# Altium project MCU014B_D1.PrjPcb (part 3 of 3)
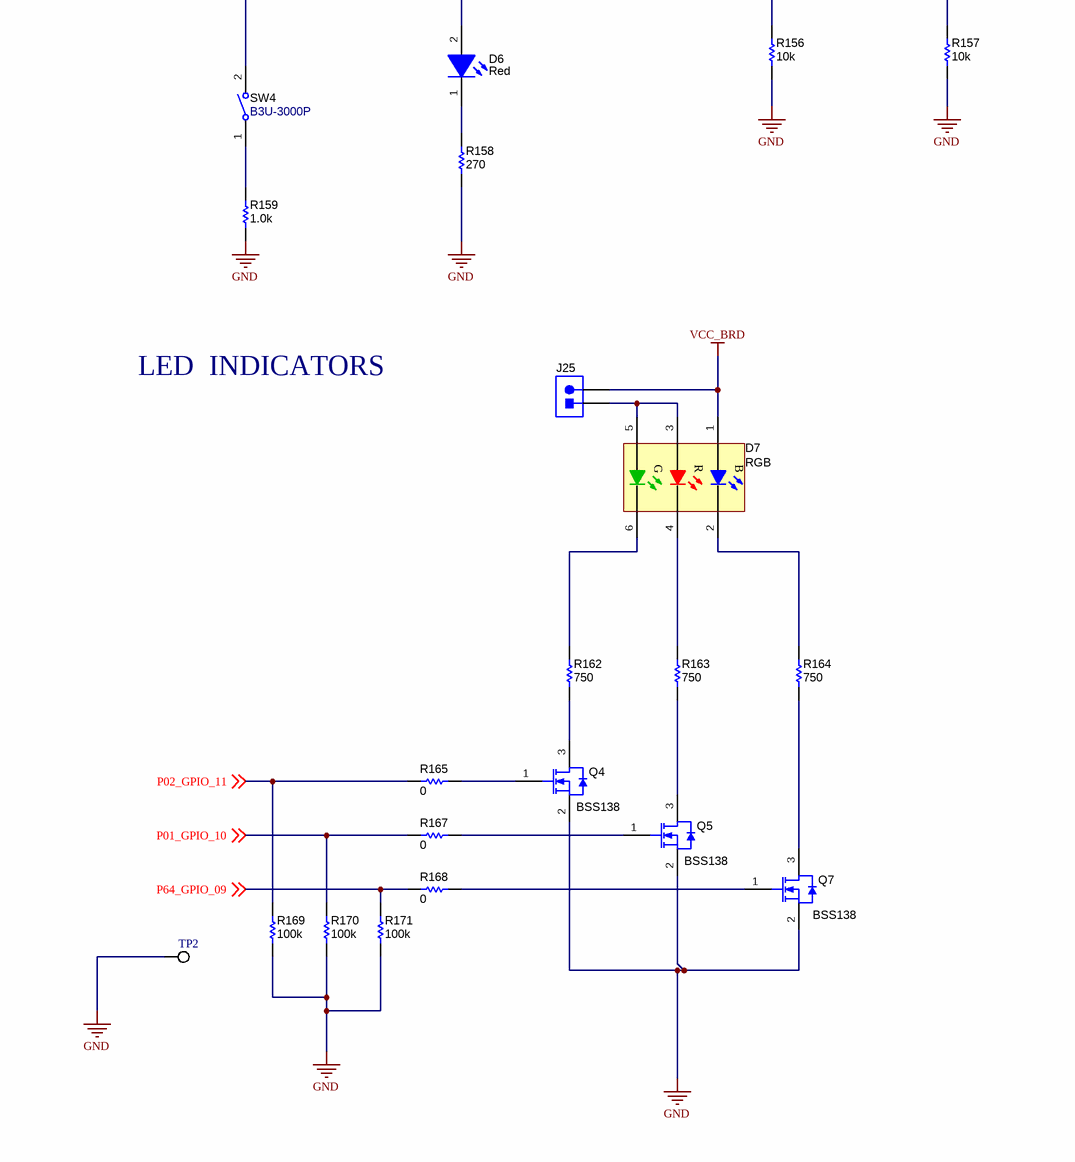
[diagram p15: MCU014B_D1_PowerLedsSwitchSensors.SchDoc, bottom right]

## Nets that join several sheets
GND: MCU014B_D1_AntennaRFSection (29 pins), MCU014B_D1_EmulationCircuit (66 pins), MCU014B_D1_EngineArea (42 pins), MCU014B_D1_HostInterface_ADC (15 pins), MCU014B_D1_PowerLedsSwitchSensors (41 pins)
VBAT_CC: MCU014B_D1_EmulationCircuit (J11.3 J11.4 R37.2), MCU014B_D1_EngineArea (13 pins), MCU014B_D1_HostInterface_ADC (R64.1), MCU014B_D1_PowerLedsSwitchSensors (5 pins)
VBUS_USB1: MCU014B_D1_EmulationCircuit (L5.2 R8.1 R15.1), MCU014B_D1_PowerLedsSwitchSensors (C80.1 J23.2 U14.2 U14.3)
VCC_5V: MCU014B_D1_HostInterface_ADC (P2.2), MCU014B_D1_PowerLedsSwitchSensors (J23.1 J27.1)
VCC_BRD: MCU014B_D1_EmulationCircuit (R35.1), MCU014B_D1_EngineArea (J14.3 R42.2), MCU014B_D1_HostInterface_ADC (J18.1 R66.1), MCU014B_D1_PowerLedsSwitchSensors (16 pins)
VCC_BUFFER: MCU014B_D1_EmulationCircuit (10 pins), MCU014B_D1_PowerLedsSwitchSensors (J22.1)
VCC_LDO_3V3: MCU014B_D1_EmulationCircuit (37 pins), MCU014B_D1_PowerLedsSwitchSensors (8 pins)
A_RX: MCU014B_D1_AntennaRFSection (C9.2), MCU014B_D1_EngineArea (U10.27)
A_TX: MCU014B_D1_AntennaRFSection (C10.2), MCU014B_D1_EngineArea (U10.28)
CC_COEX_BLE: MCU014B_D1_EngineArea (U10.50), MCU014B_D1_HostInterface_ADC (R61.1 R62.1 R101.2 R102.1)
CC_COEX_SW_OUT: MCU014B_D1_EngineArea (U10.58), MCU014B_D1_HostInterface_ADC (R60.1 R63.1 R123.2)
CC_COEX_WAKEUP: MCU014B_D1_EngineArea (U10.18), MCU014B_D1_HostInterface_ADC (R69.2 R78.1)
CC_nRESET: MCU014B_D1_EmulationCircuit (J4.10 J8.10 Q1.1 SW1.4), MCU014B_D1_EngineArea (C49.1 J13.2 R41.2 U10.32), MCU014B_D1_PowerLedsSwitchSensors (D5.1)
LP_GPIO_01: MCU014B_D1_EmulationCircuit (J9.1), MCU014B_D1_HostInterface_ADC (R91.2)
LP_GPIO_02: MCU014B_D1_EmulationCircuit (J10.1), MCU014B_D1_HostInterface_ADC (C72.1 R112.1 R116.2)
LP_RESET_OUT: MCU014B_D1_HostInterface_ADC (P1.10), MCU014B_D1_PowerLedsSwitchSensors (D5.2 R152.2)
P01_GPIO_10: MCU014B_D1_EmulationCircuit (J11.9), MCU014B_D1_EngineArea (U10.1), MCU014B_D1_HostInterface_ADC (R68.1 R98.1), MCU014B_D1_PowerLedsSwitchSensors (R132.1 R167.1 R170.1)
P02_GPIO_11: MCU014B_D1_EmulationCircuit (J11.11), MCU014B_D1_EngineArea (U10.2), MCU014B_D1_HostInterface_ADC (R67.1 R100.1), MCU014B_D1_PowerLedsSwitchSensors (R139.1 R165.1 R169.1)
P03_GPIO_12: MCU014B_D1_EngineArea (U10.3), MCU014B_D1_HostInterface_ADC (R80.1 R110.1), MCU014B_D1_PowerLedsSwitchSensors (R136.1)
P04_GPIO_13: MCU014B_D1_EngineArea (U10.4), MCU014B_D1_HostInterface_ADC (R76.1 R111.1), MCU014B_D1_PowerLedsSwitchSensors (R141.2 R143.1 R156.1 SW2.3)
P05_GPIO_14: MCU014B_D1_EngineArea (U10.5), MCU014B_D1_HostInterface_ADC (R92.1)
P06_GPIO_15: MCU014B_D1_EngineArea (U10.6), MCU014B_D1_HostInterface_ADC (R83.2 R104.2)
P07_GPIO_16: MCU014B_D1_EngineArea (U10.7), MCU014B_D1_HostInterface_ADC (R79.2 R105.2)
P08_GPIO_17: MCU014B_D1_EngineArea (U10.8), MCU014B_D1_HostInterface_ADC (R71.2)
P15_GPIO_22: MCU014B_D1_EngineArea (U10.15), MCU014B_D1_HostInterface_ADC (R95.2), MCU014B_D1_PowerLedsSwitchSensors (R157.1 SW3.3)
P16_GPIO_23: MCU014B_D1_EngineArea (R50.2), MCU014B_D1_HostInterface_ADC (R90.1 R108.1), MCU014B_D1_PowerLedsSwitchSensors (R135.1)
P16_JTAG_TDI: MCU014B_D1_EmulationCircuit (J4.2 J8.8), MCU014B_D1_EngineArea (R50.1 U10.16)
P17_GPIO_24: MCU014B_D1_EngineArea (R54.2), MCU014B_D1_HostInterface_ADC (R70.1 R94.1 R109.1), MCU014B_D1_PowerLedsSwitchSensors (R142.1)
P17_JTAG_TDO: MCU014B_D1_EmulationCircuit (J4.4 J8.6), MCU014B_D1_EngineArea (R54.1 U10.17)
P19_JTAG_TCK: MCU014B_D1_EmulationCircuit (J4.6 J8.4), MCU014B_D1_EngineArea (U10.19)
P20_JTAG_TMS: MCU014B_D1_EmulationCircuit (J4.8 J8.2), MCU014B_D1_EngineArea (U10.20)
P21_GPIO_25: MCU014B_D1_EngineArea (R55.2), MCU014B_D1_HostInterface_ADC (R75.1 R87.2)
P45_GPIO_31: MCU014B_D1_EngineArea (R47.1), MCU014B_D1_HostInterface_ADC (R73.2)
P53_GPIO_30: MCU014B_D1_EngineArea (U10.53), MCU014B_D1_HostInterface_ADC (R97.2)
P55_GPIO_01: MCU014B_D1_EmulationCircuit (J9.2 R39.1), MCU014B_D1_EngineArea (U10.55)
P57_GPIO_02: MCU014B_D1_EmulationCircuit (J10.2 R38.1), MCU014B_D1_EngineArea (U10.57)
P59_GPIO_04: MCU014B_D1_EngineArea (U10.59), MCU014B_D1_HostInterface_ADC (R65.2 R125.2)
P60_GPIO_05: MCU014B_D1_EngineArea (U10.60), MCU014B_D1_HostInterface_ADC (5 pins)
P61_GPIO_06: MCU014B_D1_EngineArea (U10.61), MCU014B_D1_HostInterface_ADC (R84.1 R107.1)
P62_GPIO_07: MCU014B_D1_EngineArea (U10.62), MCU014B_D1_HostInterface_ADC (R82.1 R96.1 R103.1)
P63_GPIO_08: MCU014B_D1_EngineArea (U10.63), MCU014B_D1_HostInterface_ADC (R93.2)
P64_GPIO_09: MCU014B_D1_EngineArea (U10.64), MCU014B_D1_HostInterface_ADC (R72.1 R99.2), MCU014B_D1_PowerLedsSwitchSensors (R168.1 R171.1)
RF_BG: MCU014B_D1_AntennaRFSection (R1.2), MCU014B_D1_EngineArea (U10.31)
SOP0: MCU014B_D1_AntennaRFSection (C14.1 U2.6), MCU014B_D1_EngineArea (C68.1 J17.2 U10.35), MCU014B_D1_PowerLedsSwitchSensors (Q2.3)
SOP1: MCU014B_D1_AntennaRFSection (C15.1 U2.4), MCU014B_D1_EngineArea (J16.2 U10.34), MCU014B_D1_PowerLedsSwitchSensors (Q2.6)

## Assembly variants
001: not fitted C1 C3 C4 C5 C11 FID1 FID2 FID3 FID4 FID5 FID6 J1 J5 J13 L1 L2 L11 Q6 R3 R14 R42 R45 R46 R64 R65 R67 R68 R70 R72 R74 R75 R78 R82 R86 R88 R102 R103 R104 R105 R106 R107 R108 R109 R110 R111 R112 R113 R120 R121 R123 R135 R136 R137 R141 R142 R143 R144 R172
002: not fitted C1 C3 C4 C5 C11 FID1 FID2 FID3 FID4 FID5 FID6 J1 J5 J13 L1 L2 Q6 R3 R14 R42 R45 R46 R47 R48 R64 R65 R67 R68 R70 R72 R74 R75 R78 R82 R86 R88 R102 R103 R104 R105 R106 R107 R108 R109 R110 R111 R112 R113 R120 R121 R123 R135 R136 R137 R141 R142 R143 R144 R172
001_SMA: not fitted C1 C3 C4 C5 C11 FID1 FID2 FID3 FID4 FID5 FID6 J3 J5 J13 L1 L2 L11 Q6 R3 R14 R42 R45 R46 R64 R65 R67 R68 R70 R72 R74 R75 R82 R86 R88 R102 R103 R104 R105 R106 R107 R108 R109 R110 R111 R112 R113 R120 R121 R123 R135 R136 R137 R141 R142 R143 R144 R172
002_SMA: not fitted C1 C3 C4 C5 C11 FID1 FID2 FID3 FID4 FID5 FID6 J3 J5 J13 L1 L2 Q6 R3 R14 R42 R45 R46 R47 R48 R64 R65 R67 R68 R70 R72 R74 R75 R82 R86 R88 R102 R103 R104 R105 R106 R107 R108 R109 R110 R111 R112 R113 R120 R121 R123 R135 R136 R137 R141 R142 R143 R144 R172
